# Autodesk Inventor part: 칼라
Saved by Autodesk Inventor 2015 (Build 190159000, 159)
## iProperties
Created: 2025-08
Part Number: 칼라
Material: 일반
Document SubType Name: Modeling
Designer: user
Density: 1 g/cm^3
Appearance: 기본값
Author: jhkim
Creation Date: 2025-08-05
Sending System: Autodesk Inventor 2026
Preprocessor: ST-DEVELOPER v20.1
Author: user
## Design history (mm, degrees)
node "칼라1"
node "솔리드1"
node "기준1"
